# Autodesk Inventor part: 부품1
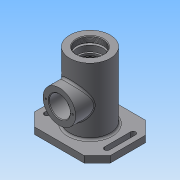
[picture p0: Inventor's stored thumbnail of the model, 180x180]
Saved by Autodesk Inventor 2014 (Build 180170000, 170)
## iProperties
Created: 2017-10
Part Number: 부품1
Material: 일반
Document SubType Name: Modeling
Designer: NET
Density: 1 g/cm^3
Appearance: 기본값
Author: NET
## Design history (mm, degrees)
sketch "스케치1"
  geometry: C1 r 31 at (0, 0); 1 further point
  constraints: 1 centre point, 1 coincident
  dimensions: "d0" = 62 diameter of C1
extrude "돌출1" new body sketch "스케치1" distance "d1" = 102; taper "d2" = 0 deg
sketch "스케치2"
  geometry: L1 (-58, 47)-(58, 47); L2 (58, 47)-(58, -47); L3 (58, -47)-(-58, -47); L4 (-58, -47)-(-58, 47); 3 further points
  constraints: 8 end point, 2 midpoint, 2 parallel, 1 horizontal, 1 horizontal alignment, 1 perpendicular, 1 vertical alignment
  dimensions: "d3" = 94 distance of L1.end L2.end; "d4" = 116 distance of L1.start L1.end
extrude "돌출2" join sketch "스케치2" distance "d5" = 10; taper "d6" = 0 deg
chamfer "모따기1" distance "d7" = 20; stored, may be unused: second distance "d8" = 2, angle "d9" = 45 deg
sketch "스케치3"
  geometry: L1 (-46, 20)-(-46, -20); L2 (-50, 20)-(-50, -20); L3 (-42, -20)-(-42, 20); L4 (-38, -47)-(-58, -27) reference; L5 (-38, -47)-(38, -47) reference; L6 (58, -27)-(38, -47) reference; L7 (58, -27)-(58, 27) reference; L8 (38, 47)-(58, 27) reference; L9 (38, 47)-(-38, 47) reference; L10 (-58, 27)-(-38, 47) reference; L11 (-58, 27)-(-58, -27) reference; C1 r 31 at (0, 0) reference; C2 r 31 at (0, 0) reference; A1 r 4 centre (-46, 20) between (-42, 20) and (-50, 20); A2 r 4 centre (-46, -20) between (-50, -20) and (-42, -20); 2 further points
  constraints: 8 end point, 4 point on circle, 4 tangent, 2 centre point, 1 horizontal alignment, 1 midpoint, 1 parallel, 1 vertical
  dimensions: "d10" = 46 distance of C1.centre point (-46, 0); "d11" = 4 radius of A1; "d12" = 20 vertical distance of L3.start point (-46, 0)
extrude "돌출3" cut sketch "스케치3" distance "d13" = 13; taper "d14" = 0 deg
sketch "스케치4"
  geometry: C1 r 35 at (0, 0); 1 further point
  constraints: 1 centre point, 1 coincident
  dimensions: "d15" = 70 diameter of C1
extrude "돌출4" join sketch "스케치4" distance "d16" = 3; taper "d17" = 0 deg
sketch "스케치5"
  geometry: L1 (0, 0)-(76, 0) reference; L2 (69, 102)-(7, 102) reference; C1 r 25 at (38, 46); 2 further points
  constraints: 1 centre point, 1 midpoint, 1 vertical alignment
  dimensions: "d18" = 50 diameter of C1; "d19" = 56 distance from line of C1.centre L2
extrude "돌출5" join sketch "스케치5" stored distance "d20" = 3; taper "d21" = 0 deg
hole "구멍1" diameter "d24" = 40.376; stored, may be unused: countersink angle "d28" = 90 deg, drill point angle "d30" = 0 deg; dims "d25" = 9, "d26" = 4, "d27" = 2, "d29" = 9, "d31" = 10, "d32" = 10
sketch "스케치6"
  geometry: L1 (0, 93)-(0, -13); L2 (-24, 93)-(-24, 90); L3 (-24, 90)-(-20, 90); L4 (-20, 90)-(-20, 81); L5 (-20, 81)-(-17.5, 81); L6 (-17.5, 81)-(-17.5, 77.75); L7 (-17.5, 77.75)-(-18.5, 77.75); L8 (-18.5, 77.75)-(-18.5, 76); L9 (-18.5, 76)-(-17.5, 76); L10 (-17.5, 76)-(-17.5, 66); L11 (-18.5, 65)-(-23, 65); L12 (-26, 62)-(-26, 30); L13 (-23, 27)-(-18.5, 27); L14 (-17.5, 26)-(-17.5, 16); L15 (-17.2, 15.7)-(-16.5, 15.7); L16 (-16.5, 15.7)-(-16.5, 13.7); L17 (-13.5, 10.7)-(-10, 10.7); L18 (-16.787, -1.096)-(-22, -13); L19 (-20.188, 102)-(20.188, 102) reference; L20 (20.188, 93)-(-20.188, 93) reference; L21 (-24, 93)-(0, 93); L22 (-35, -13)-(35, -13) reference; L23 (-14.039, 0.7)-(-12.904, 0.7); L24 (-12.5, 1.4)-(-12.5, 7.7); L25 (-12.2, 8)-(-10, 8); L26 (-10, 8)-(-10, 10.7); L27 (-22, -13)-(0, -13); L28 (-17.5, 66)-(-18.5, 65); L29 (-18.5, 27)-(-17.5, 26); L30 (-12.5, 1.4)-(-12.904, 0.7); A1 r 0.3 centre (-12.2, 7.7) between (-12.2, 8) and (-12.5, 7.7); A2 r 3 centre (-23, 62) between (-23, 65) and (-26, 62); A3 r 3 centre (-23, 30) between (-26, 30) and (-23, 27); A4 r 3 centre (-13.5, 13.7) between (-16.5, 13.7) and (-13.5, 10.7); A5 r 0.3 centre (-17.2, 16) between (-17.5, 16) and (-17.2, 15.7); A6 r 3 centre (-14.039, -2.3) between (-14.039, 0.7) and (-16.787, -1.096); 10 further points
  constraints: 56 end point, 23 point on line, 14 parallel, 12 point on circle, 12 tangent, 6 centre point, 4 perpendicular, 3 collinear, 2 midpoint, 2 vertical, 1 equal radius, 1 horizontal
  dimensions: "d34" = 48 diameter of L2 L1; "d35" = 3 distance of L2.start L2.end; "d36" = 21 distance between parallel lines of L5 L19; "d38" = 1.75 distance of L7.end L8.end; "d39" = 37 diameter of L8 L1; "d40" = 11 distance of L9.end point (-17.5, 65); "d41" = 35 diameter of L10 L1; "d42" = 38 distance of point (-26, 65) point (-26, 27); "d43" = 35 diameter of L14 L1; "d44" = 52 diameter of L12 L1; "d47" = 44 diameter of L18.end L1; "d48" = 32 diameter of point (-16, 0.7) L1; "d53" = 7.3 distance of point (-12.5, 0.7) point (-12.5, 8); "d54" = 2.7 distance of L25.end L17.end; "d55" = 20 diameter of L26 L1; "d56" = 25 diameter of L24 L1; "d57" = 0.3 radius of A1; "d60" = 40 diameter of L4 L1; "d61" = 35 diameter of L6 L1; "d63" = 26 distance between parallel lines of L19 L9; "d66" = 33 diameter of L16 L1; "d67" = 5 distance of L15.end point (-16.5, 10.7); "d103" = 3 radius of A2; "d104" = 1 distance of L10.end point (-17.5, 65); "d105" = 1 distance of L11.start point (-17.5, 65) (= d104); "d106" = 1 distance of L13.end point (-17.5, 27) (= d104); "d107" = 1 distance of L14.start point (-17.5, 27) (= d106); "d108" = 3 radius of A4; "d109" = 0.3 radius of A5; "d110" = 3 radius of A6; "d111" = 0.7 distance of L24.start point (-12.5, 0.7); "d112" = 30 deg angle of L24 L30
revolve "회전1" sketch "스케치6" stored, may be unused: angle "d68" = 90 deg
hole "구멍2" diameter "d71" = 32; stored, may be unused: countersink angle "d75" = 90 deg, drill point angle "d77" = 0 deg; dims "d72" = 9, "d73" = 4, "d74" = 2, "d76" = 40, "d78" = 10, "d79" = 10
sketch "스케치7" dims "d80" = 41
  geometry: C1 r 16 at (0, 0) reference; 3 further points
  constraints: 2 horizontal alignment, 1 coincident, 2 other
hole "구멍3" sketch "스케치7" at (20.5, 0) diameter "d81" = 2.459; stored, may be unused: countersink angle "d85" = 90 deg, drill point angle "d87" = 118 deg; dims "d82" = 6, "d83" = 4, "d84" = 2, "d86" = 8
sketch "스케치8"
  geometry: L1 (102, -4)-(102, 58) reference; L2 (71, -20)-(21, -20) reference; 2 further points
  constraints: 1 other
  dimensions: "d93" = 56 distance from line of point (46, -10) L1; "d94" = 10 distance from line of point (46, -10) L2
feature "엠보싱1" sketch "스케치8" dims "d91" = 0.5, "d92" = 0
chamfer "모따기3" distance "d98" = 1; stored, may be unused: second distance "d99" = 2, angle "d100" = 45 deg
fillet "모깎기1" dims "d101" = 3
node "솔리드1"
mirror "대칭1"
pattern_circular "원형 패턴1" dims angle "d89" = 360 deg
node "투영된 루프1"
node "투영된 루프2"
node "투영된 루프3"
